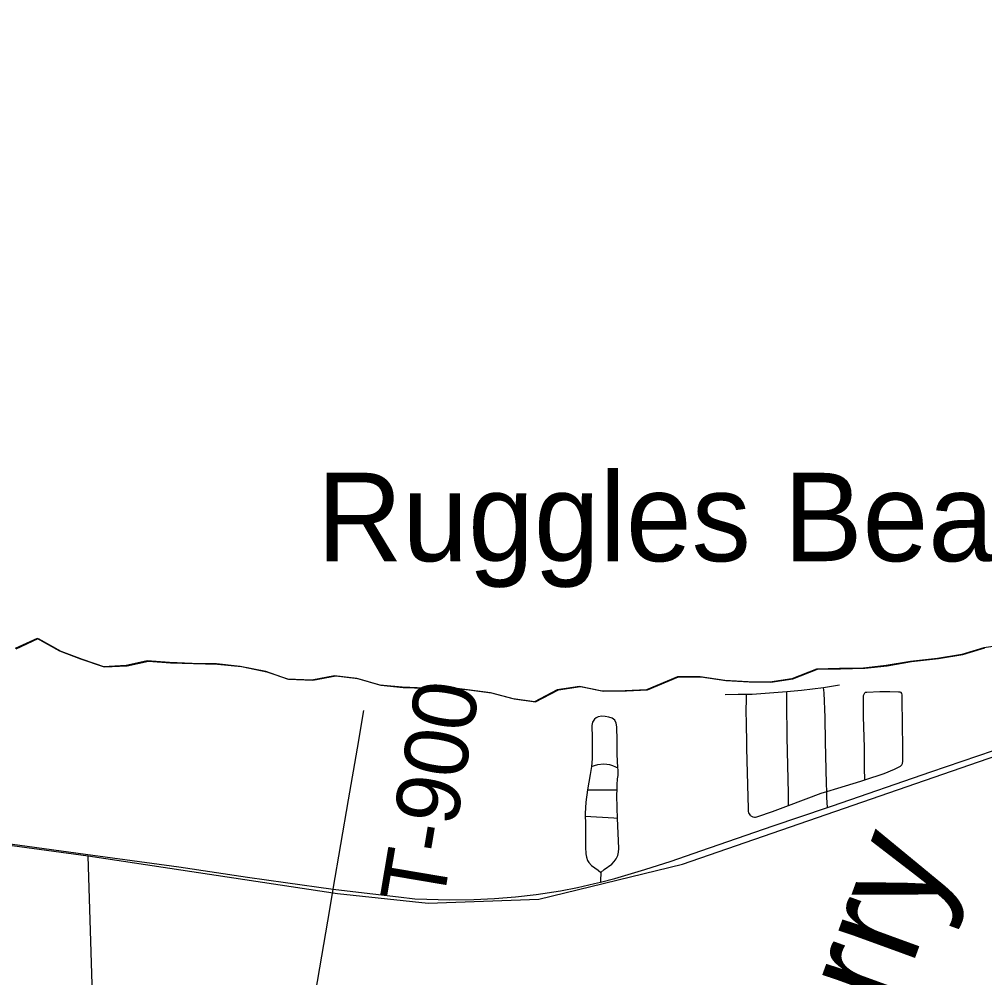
# Model space of a CAD drawing. Extents: x 0 to 34, y 0 to 22.
# Drawn here: x 6.817 to 7.68, y 18.183 to 19.039 of the extents above; entities that cross this region are included whole.
import ezdxf

# ---------------------------------------------------------------- set-up
doc = ezdxf.new("R2010")
doc.units = 0
for name, color, linetype in [('GM_X_Corporation', 7, 'Continuous'), ('GM_X_Major_Lake', 7, 'Continuous'), ('GM_X_Minor_River_Text', 7, 'Continuous'), ('GM_X_Rail_Line', 7, 'Continuous'), ('GM_X_State_Route', 7, 'Continuous'), ('GM_X_Township_Road', 7, 'Continuous'), ('GM_X_Township_Road_Text', 7, 'Continuous'), ('GM_X_Unincorporated_Text', 7, 'Continuous'), ('GM_X_US_Route', 7, 'Continuous')]:
    doc.layers.add(name, color=color, linetype=linetype)

msp = doc.modelspace()

# ---------------------------------------------------------------- linework, layer by layer
at = {"layer": 'GM_X_Corporation'}
msp.add_lwpolyline([(7.69796, 18.48081), (7.67899, 18.47815), (7.65926, 18.47207), (7.63762, 18.46865), (7.61333, 18.46599), (7.5917, 18.4622), (7.57158, 18.45992), (7.54995, 18.45954), (7.52945, 18.45916), (7.50744, 18.45042), (7.48771, 18.44738), (7.46835, 18.44776), (7.44748, 18.4489), (7.42547, 18.45232), (7.40535, 18.45232), (7.37765, 18.44054), (7.35867, 18.43979), (7.33818, 18.43941), (7.31768, 18.44359), (7.29794, 18.44054), (7.27745, 18.42991), (7.25847, 18.43257), (7.23836, 18.43789), (7.21787, 18.44054), (7.19851, 18.44282), (7.17953, 18.44207), (7.15942, 18.44282), (7.13931, 18.44473), (7.11881, 18.4508), (7.09907, 18.45308), (7.07858, 18.44929), (7.05694, 18.45004), (7.03759, 18.45688), (7.01482, 18.46144), (6.99356, 18.46372), (6.97193, 18.4641), (6.95144, 18.46486), (6.9317, 18.46638), (6.91272, 18.4622), (6.89261, 18.46106), (6.8725, 18.4679), (6.85352, 18.47512), (6.83341, 18.48651), (6.81367, 18.47739)], dxfattribs=at)
msp.add_lwpolyline([(7.69796, 18.48081), (7.67899, 18.47815), (7.65926, 18.47207), (7.63762, 18.46865), (7.61333, 18.46599), (7.5917, 18.4622), (7.57158, 18.45992), (7.54995, 18.45954), (7.52945, 18.45916), (7.50744, 18.45042), (7.48771, 18.44738), (7.46835, 18.44776), (7.44748, 18.4489), (7.42547, 18.45232), (7.40535, 18.45232), (7.37765, 18.44054), (7.35867, 18.43979), (7.33818, 18.43941), (7.31768, 18.44359), (7.29794, 18.44054), (7.27745, 18.42991), (7.25847, 18.43257), (7.23836, 18.43789), (7.21787, 18.44054), (7.19851, 18.44282), (7.17953, 18.44207), (7.15942, 18.44282), (7.13931, 18.44473), (7.11881, 18.4508), (7.09907, 18.45308), (7.07858, 18.44929), (7.05694, 18.45004), (7.03759, 18.45688), (7.01482, 18.46144), (6.99356, 18.46372), (6.97193, 18.4641), (6.95144, 18.46486), (6.9317, 18.46638), (6.91272, 18.4622), (6.89261, 18.46106), (6.8725, 18.4679), (6.85352, 18.47512), (6.83341, 18.48651), (6.81367, 18.47739)], dxfattribs=at)
at = {"layer": 'GM_X_Major_Lake'}
msp.add_lwpolyline([(6.81463, 18.47731), (6.83437, 18.48642), (6.85448, 18.47503), (6.87346, 18.46781), (6.89357, 18.46097), (6.91369, 18.46211), (6.93267, 18.46629), (6.9524, 18.46477), (6.97289, 18.46401), (6.99453, 18.46363), (7.01578, 18.46135), (7.03855, 18.45679), (7.05791, 18.44995), (7.07954, 18.4492), (7.10004, 18.45299), (7.11977, 18.45071), (7.14027, 18.44464), (7.16038, 18.44274), (7.1805, 18.44198), (7.19947, 18.44274), (7.21883, 18.44046), (7.23932, 18.4378), (7.25944, 18.43248), (7.27842, 18.42982), (7.29891, 18.44046), (7.31864, 18.4435), (7.33914, 18.43932), (7.35963, 18.4397), (7.37861, 18.44046), (7.40631, 18.45223), (7.42643, 18.45223), (7.44844, 18.44881), (7.46932, 18.44767), (7.48867, 18.4473), (7.50841, 18.45033), (7.53042, 18.45907), (7.55091, 18.45945), (7.57255, 18.45983), (7.59266, 18.46211), (7.6143, 18.46591), (7.63859, 18.46857), (7.66022, 18.47198), (7.67995, 18.47806)], dxfattribs=at)
at = {"layer": 'GM_X_Rail_Line'}
for points in [[(4.15567, 19.03949), (4.37138, 19.02191), (4.47313, 19.01067), (4.54928, 18.99506), (4.89823, 18.92512), (4.98063, 18.91388), (5.294, 18.88266), (5.32646, 18.87516), (5.65418, 18.7278), (5.78776, 18.66785), (5.83708, 18.63913), (6.0231, 18.51611), (6.12922, 18.44618), (6.17604, 18.41808), (6.22535, 18.39685), (6.27716, 18.37936), (6.48815, 18.34502), (6.68791, 18.31816), (6.87885, 18.29227)], [(6.87885, 18.29227), (7.10148, 18.25871), (7.18271, 18.24997), (7.28141, 18.25347), (7.4098, 18.28492), (7.96356, 18.47627), (8.07536, 18.5051), (8.3304, 18.56189), (8.37494, 18.56451), (8.45443, 18.56888), (8.5243, 18.58723), (8.9, 18.69387)], [(6.92531, 17.80414), (6.90838, 17.881), (6.88672, 18.04362), (6.87885, 18.29227)]]:
    msp.add_lwpolyline(points, dxfattribs=at)
at = {"layer": 'GM_X_State_Route'}
msp.add_lwpolyline([(7.01249, 17.76638), (7.01717, 17.79385), (7.01883, 17.80358), (7.02502, 17.83981), (7.0273, 17.85391), (7.02997, 17.8705), (7.04514, 17.95623), (7.06477, 18.0696), (7.07476, 18.12784), (7.09466, 18.24431), (7.09782, 18.2626)], dxfattribs=at)
at = {"layer": 'GM_X_Township_Road'}
msp.add_line((7.53574, 18.44275), (7.54998, 18.44511), dxfattribs=at)
for points in [[(7.467, 18.4366), (7.47194, 18.4366), (7.4915, 18.43818), (7.50304, 18.43916)], [(7.50304, 18.43916), (7.51622, 18.44027), (7.53574, 18.44275)], [(7.50462, 18.33711), (7.5044, 18.34821), (7.50343, 18.39785), (7.50314, 18.42891), (7.50304, 18.43916)], [(7.53865, 18.34987), (7.53839, 18.35692), (7.53744, 18.39422), (7.53724, 18.41598), (7.53647, 18.43775), (7.53574, 18.44275)], [(7.57255, 18.36014), (7.57244, 18.37046), (7.57226, 18.38894), (7.57158, 18.41671), (7.57138, 18.43215), (7.57156, 18.43554), (7.57193, 18.43681), (7.57262, 18.43783)], [(7.57262, 18.43783), (7.57338, 18.43834), (7.57453, 18.43844), (7.58599, 18.43901), (7.59497, 18.43899), (7.60266, 18.4388), (7.60405, 18.43865), (7.60469, 18.43852), (7.60526, 18.43821)], [(7.60576, 18.37356), (7.60623, 18.37478), (7.60669, 18.37695), (7.60675, 18.38863), (7.60599, 18.43163), (7.60589, 18.43617), (7.60576, 18.43739), (7.60526, 18.43821)], [(7.44789, 18.43647), (7.45963, 18.4366), (7.467, 18.4366)], [(7.47073, 18.32808), (7.46952, 18.32971), (7.4691, 18.3308), (7.46885, 18.33196), (7.46876, 18.33496), (7.46844, 18.34481), (7.4674, 18.38842), (7.46713, 18.39761), (7.46707, 18.4057), (7.46696, 18.40998), (7.46675, 18.42242), (7.46692, 18.43176), (7.467, 18.4366)], [(7.09782, 18.2626), (7.11157, 18.34238), (7.11938, 18.38836), (7.12521, 18.42206)], [(7.35216, 18.37098), (7.35138, 18.383), (7.3513, 18.39534), (7.35122, 18.40766), (7.35069, 18.41072), (7.34935, 18.41342), (7.34697, 18.41518), (7.344, 18.41625), (7.34078, 18.41678), (7.3376, 18.41691), (7.33456, 18.4165), (7.33255, 18.4156), (7.33115, 18.41425), (7.32955, 18.41159), (7.32885, 18.40876), (7.32905, 18.39771), (7.329, 18.38978), (7.329, 18.38605), (7.329, 18.37891), (7.32838, 18.37207)], [(7.32838, 18.37207), (7.32726, 18.36482), (7.32493, 18.35116)], [(7.32838, 18.37207), (7.33117, 18.37301), (7.33402, 18.37387), (7.33911, 18.37438), (7.3422, 18.37422), (7.3447, 18.37383), (7.34741, 18.3729), (7.34981, 18.37192), (7.35216, 18.37098)], [(7.35129, 18.35125), (7.35139, 18.3556), (7.35188, 18.36114), (7.35232, 18.36391), (7.35232, 18.36896), (7.35216, 18.37098)], [(7.57255, 18.36014), (7.58979, 18.36576), (7.59918, 18.36963), (7.60339, 18.37173), (7.60466, 18.37236), (7.60576, 18.37356)], [(7.53865, 18.34987), (7.54844, 18.35285), (7.5692, 18.35904), (7.57255, 18.36014)], [(7.32493, 18.35116), (7.32352, 18.34016), (7.32275, 18.33005), (7.32275, 18.32765)], [(7.32493, 18.35116), (7.32728, 18.35118), (7.34742, 18.35123), (7.35129, 18.35125)], [(7.35159, 18.32601), (7.3514, 18.33486), (7.35118, 18.34691), (7.35129, 18.35125)], [(7.50462, 18.33711), (7.53365, 18.34834), (7.53865, 18.34987)], [(7.53921, 18.33544), (7.53886, 18.34448), (7.53865, 18.34987)], [(7.47073, 18.32808), (7.47254, 18.32724), (7.47399, 18.32694), (7.47514, 18.32683), (7.47621, 18.32709), (7.47706, 18.3273), (7.49023, 18.332), (7.50462, 18.33711)], [(7.32275, 18.32765), (7.34849, 18.32625), (7.35159, 18.32601)], [(7.32275, 18.32765), (7.32306, 18.32221), (7.32321, 18.31398), (7.32321, 18.30473), (7.3232, 18.29993), (7.32359, 18.29418), (7.32415, 18.29116), (7.3249, 18.28821), (7.32608, 18.28638), (7.32849, 18.28377), (7.33453, 18.27962), (7.33689, 18.27726)], [(7.33689, 18.27726), (7.33996, 18.28), (7.34669, 18.28488), (7.34887, 18.28708), (7.35061, 18.28964), (7.35189, 18.29248), (7.3527, 18.29545), (7.35288, 18.29896), (7.35159, 18.32601)], [(7.33689, 18.27726), (7.3367, 18.27538), (7.33667, 18.27216), (7.33664, 18.26883)]]:
    msp.add_lwpolyline(points, dxfattribs=at)
at = {"layer": 'GM_X_US_Route'}
for points in [[(7.09782, 18.2626), (7.10023, 18.26231), (7.13324, 18.25843), (7.15598, 18.25566), (7.17068, 18.25399), (7.18148, 18.25346), (7.20159, 18.25301), (7.22335, 18.25332), (7.242, 18.25418), (7.26061, 18.25565), (7.27914, 18.25788), (7.30067, 18.26116), (7.31597, 18.264), (7.33114, 18.26743), (7.33664, 18.26883), (7.34923, 18.27203), (7.37607, 18.27995), (7.39973, 18.2876), (7.42617, 18.29669), (7.49073, 18.31904), (7.53921, 18.33544), (7.54369, 18.33696), (7.63175, 18.36742), (7.68764, 18.38635)], [(6.80272, 18.30383), (6.87664, 18.29384), (6.95976, 18.28234), (7.02126, 18.27337), (7.05522, 18.26844), (7.09782, 18.2626)]]:
    msp.add_lwpolyline(points, dxfattribs=at)

# ---------------------------------------------------------------- texts
at = {"layer": 'GM_X_Minor_River_Text'}
msp.add_text('Cranberry', height=0.094754, rotation=69.99971, dxfattribs=at).set_placement((7.45796, 17.76263))
at = {"layer": 'GM_X_Township_Road_Text'}
msp.add_text('T-900', height=0.056818, rotation=80.39919, dxfattribs=at).set_placement((7.1956, 18.24678))
at = {"layer": 'GM_X_Unincorporated_Text'}
msp.add_text('Ruggles Beach', height=0.0789773, rotation=0.00001, dxfattribs=at).set_placement((7.08334, 18.55548))

doc.saveas('drawing.dxf')
